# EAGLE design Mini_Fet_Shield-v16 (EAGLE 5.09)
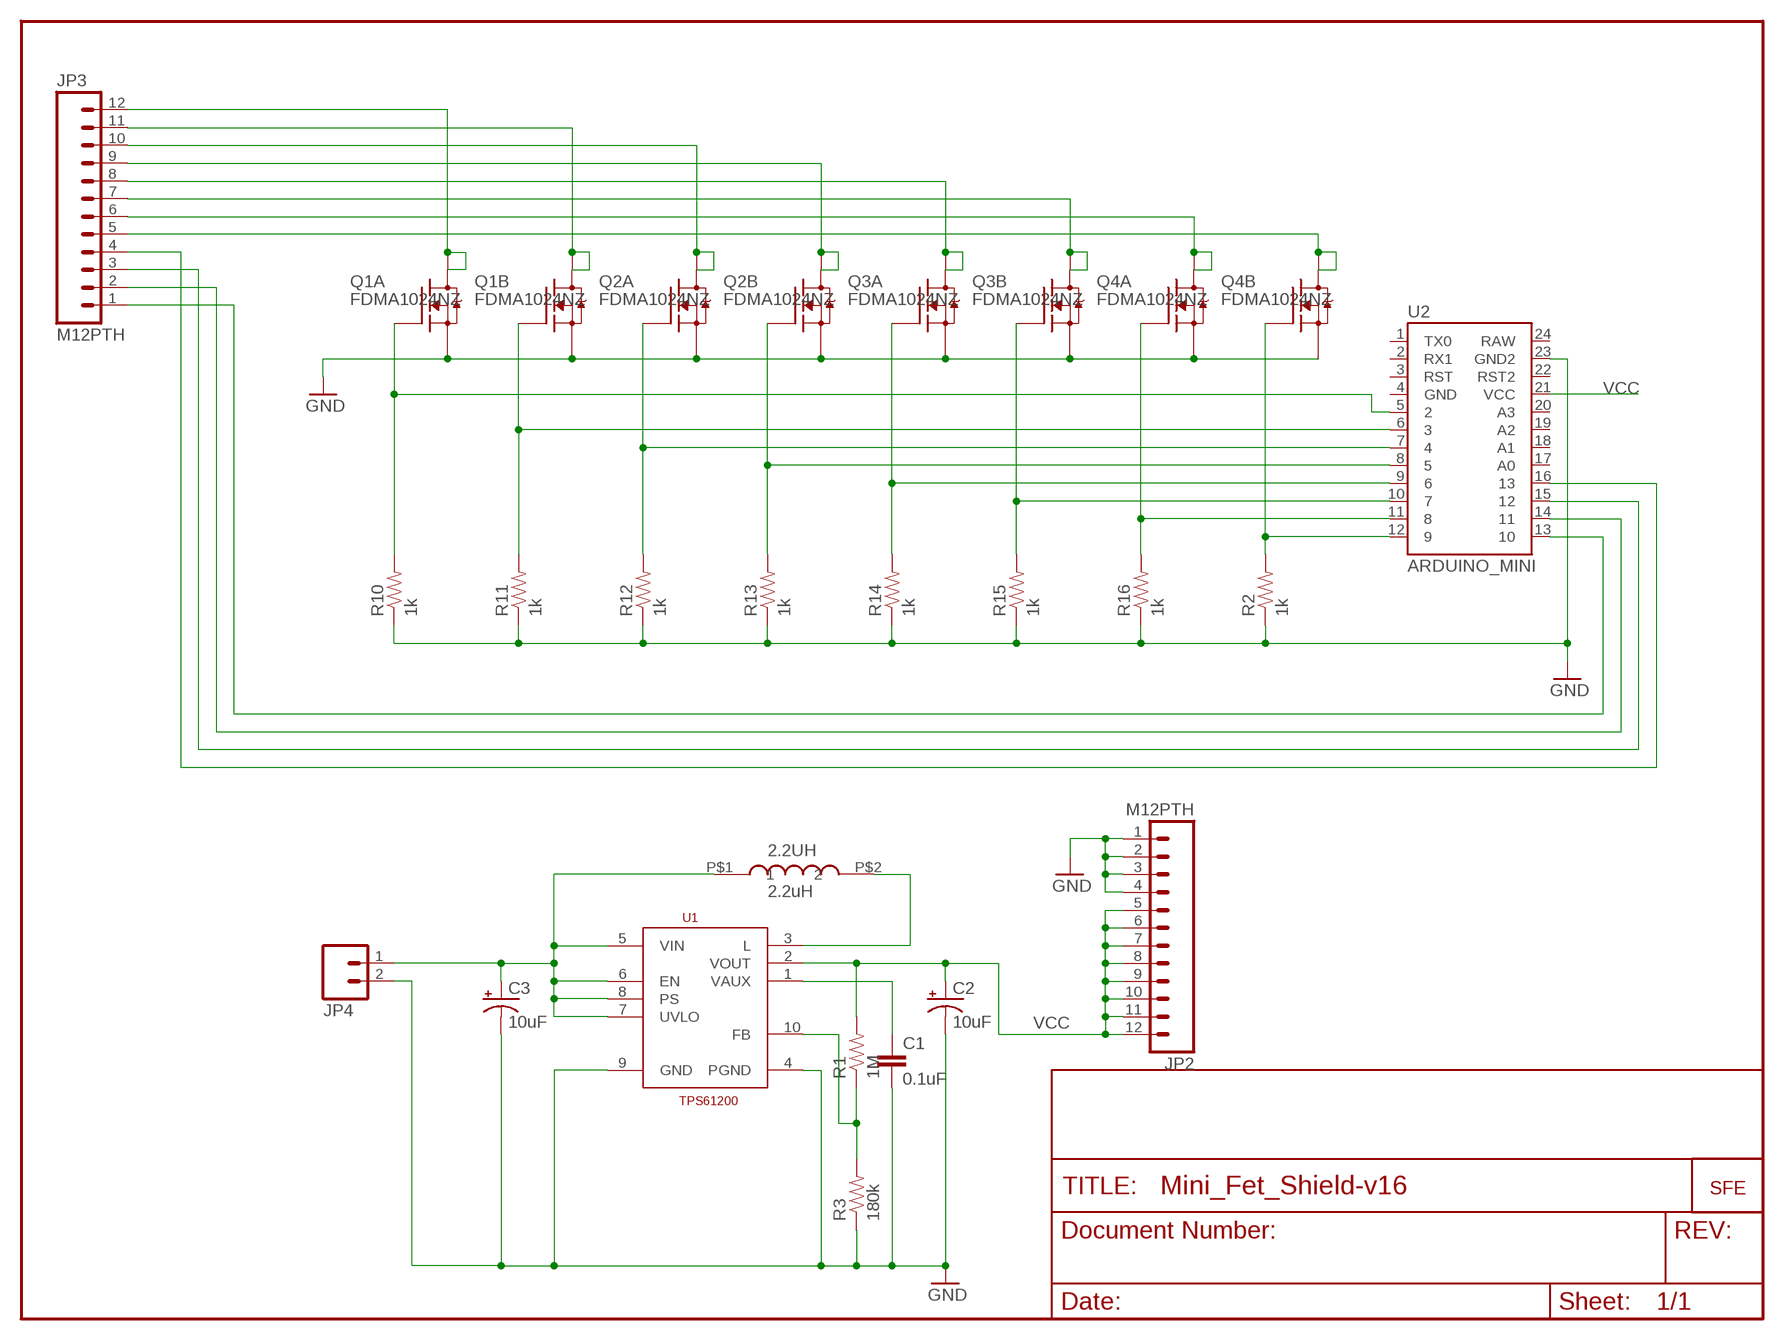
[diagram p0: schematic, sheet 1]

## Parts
2.2UH  2.2uH  VLF4012A  [VLF4012A]
C1  0.1uF  CAP0402-CAP  [0402-CAP]
C2  10uF  CAP_POL1206  [EIA3216]
C3  10uF  CAP_POL1206  [EIA3216]
JP2  M12PTH  [1X12]
JP3  M12PTH  [1X12]
JP4  M02PTH  [1X02]
JP5  LOGO-SFESK  [SFE-LOGO-FLAME]
Q1  FDMA1024NZ  [MICROFET_2X2]
Q2  FDMA1024NZ  [MICROFET_2X2]
Q3  FDMA1024NZ  [MICROFET_2X2]
Q4  FDMA1024NZ  [MICROFET_2X2]
R1  1M  RESISTOR0402-RES  [0402-RES]
R2  1k  RESISTOR0402-RES  [0402-RES]
R3  180k  RESISTOR0402-RES  [0402-RES]
R10  1k  RESISTOR0402-RES  [0402-RES]
R11  1k  RESISTOR0402-RES  [0402-RES]
R12  1k  RESISTOR0402-RES  [0402-RES]
R13  1k  RESISTOR0402-RES  [0402-RES]
R14  1k  RESISTOR0402-RES  [0402-RES]
R15  1k  RESISTOR0402-RES  [0402-RES]
R16  1k  RESISTOR0402-RES  [0402-RES]
U1  TPS61200  [DRC-S-PVSON-N10]
U2  ARDUINO_MINI  [ARDUINO_MINI]

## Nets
GND: C1.2 C2.C(-) C3.C(-) JP2.1 JP2.2 JP2.3 JP2.4 JP4.2 Q1.S1(A:S) Q1.S2(B:S) Q2.S1(A:S) Q2.S2(B:S) Q3.S1(A:S) Q3.S2(B:S) Q4.S1(A:S) Q4.S2(B:S) R2.1 R3.1 R10.1 R11.1 R12.1 R13.1 R14.1 R15.1 R16.1 U1.4(PGND) U1.9(GND) U2.23(GND2)
N$1: JP3.4 U2.16
N$2: R1.1 R3.2 U1.10(FB)
N$3: C1.1 U1.1(VAUX)
N$5: 2.2UH.P$2 U1.3(L)
N$7: Q1.G1(A:G) R10.2 U2.5
N$8: 2.2UH.P$1 C3.A(+) JP4.1 U1.5(VIN) U1.6(EN) U1.7(UVLO) U1.8(PS)
N$10: Q1.G2(B:G) R11.2 U2.6
N$11: Q2.G1(A:G) R12.2 U2.7
N$12: Q2.G2(B:G) R13.2 U2.8
N$13: Q3.G1(A:G) R14.2 U2.9
N$14: Q3.G2(B:G) R15.2 U2.10
N$15: Q4.G1(A:G) R16.2 U2.11
N$16: Q4.G2(B:G) R2.2 U2.12
N$17: JP3.12 Q1.D1(A:D) Q1.D1_2(A:D1)
N$18: JP3.11 Q1.D2(B:D) Q1.D2_2(B:D1)
N$19: JP3.10 Q2.D1(A:D) Q2.D1_2(A:D1)
N$20: JP3.9 Q2.D2(B:D) Q2.D2_2(B:D1)
N$21: JP3.8 Q3.D1(A:D) Q3.D1_2(A:D1)
N$22: JP3.7 Q3.D2(B:D) Q3.D2_2(B:D1)
N$23: JP3.6 Q4.D1(A:D) Q4.D1_2(A:D1)
N$24: JP3.5 Q4.D2(B:D) Q4.D2_2(B:D1)
N$25: JP3.3 U2.15
N$26: JP3.2 U2.14
N$27: JP3.1 U2.13
VCC: C2.A(+) JP2.5 JP2.6 JP2.7 JP2.8 JP2.9 JP2.10 JP2.11 JP2.12 R1.2 U1.2(VOUT) U2.21(VCC)
Unconnected: U2.1(TX0) U2.2(RX1) U2.3(RST) U2.4(GND) U2.17(A0) U2.18(A1) U2.19(A2) U2.20(A3) U2.22(RST2) U2.24(RAW)

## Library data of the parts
2.2UH = PEBBLE:VLF4012A
C1 = SparkFun:CAP: Capacitor
C2 C3 = SparkFun:CAP_POL: Capacitor Polarized
JP2 JP3 = SparkFun:M12: Header 12 Standard 12-pin 0.1" header. Use with straight break away headers (SKU : PRT-00116), right angle break away headers (PRT-00553), swiss pins (PRT-00743), machine pins (PRT-00117), and female headers (PRT-00115).
JP4 = SparkFun:M02: Header 2
JP5 = SparkFun:LOGO-SFE: Spark Fun Electronics PCB Logo
Q1-Q4 = PEBBLE:FDMA1024NZ: Dual N-Channel 30-V (D-S) MOSFET Source: http://www.vishay.com/docs/71053/71053.pdf
R1-R3 R10-R16 = SparkFun:RESISTOR: Resistor
U1 = texas:TPS61200
U2 = SparkFun:ARDUINO_MINI

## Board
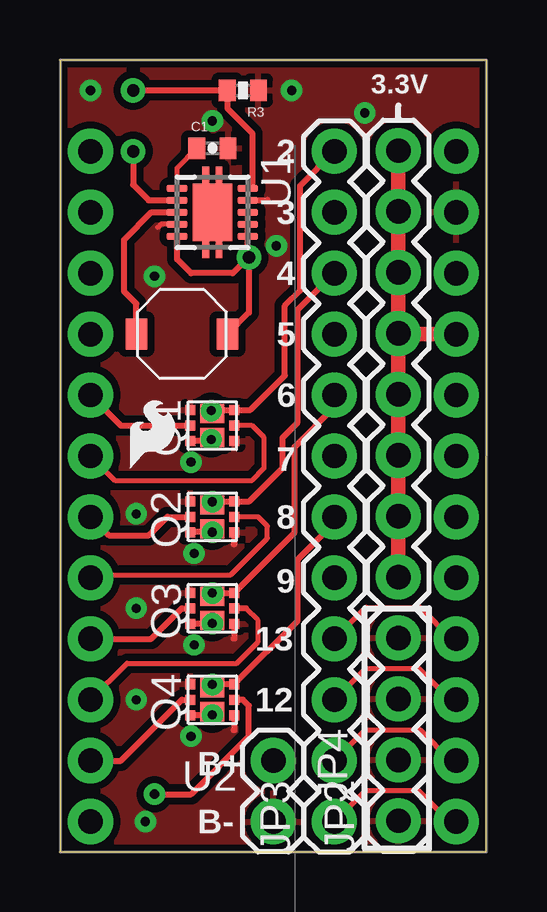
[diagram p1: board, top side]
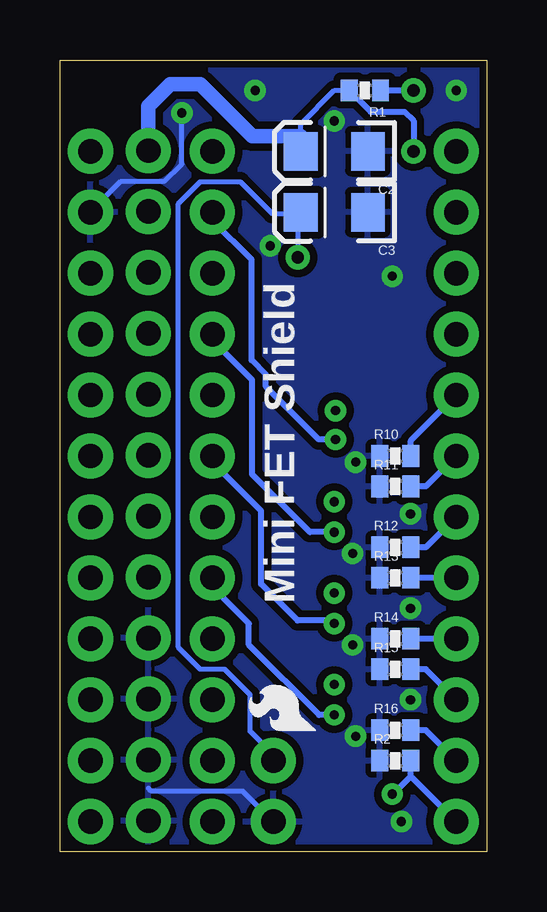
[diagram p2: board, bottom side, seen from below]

Size 17.78 x 33.02 mm. Coordinates in mm from the lower left corner, seen from the top.
Outline: 0,0 17.76,0 17.78,33.02 0,33.02 0,0
Copper layers (1*16): Top 0.035mm / dielectric 1.5mm / Bottom 0.035mm
Design rules "SparkFun": minimum track width 8mil, minimum drill 20mil, track to track 8mil, track to pad 8mil, pad to pad 8mil, via to via 8mil, smd to smd 8mil, copper to edge 8mil, drill to drill 8mil, minimum pad ring 12mil, minimum via ring 10mil, stop-mask expansion 4mil, vias tented up to drill 20mil, thermal gap 10mil

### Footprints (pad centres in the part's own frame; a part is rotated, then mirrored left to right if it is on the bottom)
VLF4012A = smd 0.9 x 1.3: P$1 -1.9,0; P$2 1.9,0
0402-CAP = smd 0.7 x 0.9: 1 -0.65,0; 2 0.65,0
EIA3216 = smd 1.4 x 1.6: A 1.4,0; C -1.4,0
1X12 = drill 1.016 pad 1.88 round: 1 0,0; 2 2.54,0; 3 5.08,0; 4 7.62,0; 5 10.16,0; 6 12.7,0; 7 15.24,0; 8 17.78,0; 9 20.32,0; 10 22.86,0; 11 25.4,0; 12 27.94,0
1X02 = drill 1.016 pad 1.88 round: 1 0,0; 2 2.54,0
MICROFET_2X2 = smd 0.8 x 1: D1 0.5,0; D2 -0.5,0 | smd 0.42 x 0.42: D1_2 0.65,-0.915; D2_2 -0.65,0.915; G1 0,0.915; G2 0,-0.915; S1 0.65,0.915; S2 -0.65,-0.915
0402-RES = smd 0.7 x 0.9: 1 -0.65,0; 2 0.65,0
DRC-S-PVSON-N10 = smd 0.28 x 0.85: 1 -1,-1.475; 2 -0.5,-1.475; 3 0,-1.475; 4 0.5,-1.475; 5 1,-1.475; 6 1,1.475; 7 0.5,1.475; 8 0,1.475; 9 -0.5,1.475; 10 -1,1.475 | smd 2.4 x 1.65: TH 0,0 | smd 3.8 x 0.28: TH@1 0,0.275; TH@2 0,-0.275
ARDUINO_MINI = drill 1.016 pad 1.88 round: 1 -7.62,12.7; 2 -7.62,10.16; 3 -7.62,7.62; 4 -7.62,5.08; 5 -7.62,2.54; 6 -7.62,0; 7 -7.62,-2.54; 8 -7.62,-5.08; 9 -7.62,-7.62; 10 -7.62,-10.16; 11 -7.62,-12.7; 12 -7.62,-15.24; 13 7.62,-15.24; 14 7.62,-12.7; 15 7.62,-10.16; 16 7.62,-7.62; 17 7.62,-5.08; 18 7.62,-2.54; 19 7.62,0; 20 7.62,2.54; 21 7.62,5.08; 22 7.62,7.62; 23 7.62,10.16; 24 7.62,12.7

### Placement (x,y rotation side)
2.2UH  5.08,21.59 180 top
C1  6.35,29.34 0 top
C2  6.35,29.21 180 bottom
C3  6.35,26.67 180 bottom
JP1  LOGO-SFESK  [SFE-LOGO-FLAME]  2.92,16 0 top
JP2  14.1,1.3 90 top
JP3  11.43,1.27 90 top
JP4  8.89,3.81 270 top
JP5  7.11,5.08 90 bottom
Q1  6.35,17.78 90 top
Q2  6.35,13.97 90 top
Q3  6.35,10.16 90 top
Q4  6.35,6.35 90 top
R1  5.08,31.75 180 bottom
R2  3.81,3.81 0 bottom
R3  7.62,31.75 180 top
R10  3.81,16.51 0 bottom
R11  3.81,15.24 0 bottom
R12  3.81,12.7 0 bottom
R13  3.81,11.43 0 bottom
R14  3.81,8.89 0 bottom
R15  3.81,7.62 0 bottom
R16  3.81,5.08 0 bottom
U1  6.35,26.67 270 top
U2  8.89,16.51 0 top

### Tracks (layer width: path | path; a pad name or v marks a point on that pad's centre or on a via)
GND  (via drill 0.38)
  Top 0.203: U1.4 4.2,26.17 4.06,26.04
  Top 0.254: Q4.S2 7.26,5.08 7.24,5.08 | Q3.S2 7.26,8.89 7.24,8.89 | Q2.S2 7.26,12.83 7.24,12.83 | U1.9 8.64,27.18
  Bottom 0.203: JP4.2 10.16,2.54 13.97,2.54 14.1,2.67 | U2.23 15.24,27.96 13.44,27.96 12.7,28.68 12.7,30.68 12.72,30.71
  other vias: 3.56,1.27 3.17,14.1 3.17,10.16 3.17,6.35 5.46,16.26 5.59,12.45 5.59,8.64 1.27,31.75 5.46,4.83 3.94,24 9.65,31.75 6.35,30.48 9.02,25.27 12.7,30.81
  pour Top (isolate 0.305): 0,33.02 0,0 17.78,0 17.78,33.02
  pour Bottom (isolate 0.305): 0,33.02 0,0 17.78,0 17.78,33.02
N$1
  Top 0.203: U2.16 16.31,8.89 15,10.2 12.74,10.2 JP3.4
N$2  (via drill 0.51)
  Top 0.254: v3.05,31.75 R3.2 6.97,31 8,29.97 8,27.85 U1.10
  Bottom 0.254: R1.1 v3.05,31.75
N$3
  Top 0.203: U1.1 4.88,28.51 C1.1
N$5
  Top 0.254: U1.3 3.81,26.67 2.67,25.53 2.67,23.37 3.18,22.86 2.2UH.P$2
N$7
  Top 0.254: Q1.G1 2.54,17.78 U2.5
  Bottom 0.254: R10.2 3.16,17.16 U2.5
N$8  (via drill 0.51)
  Top 0.203: U1.8 7.82,26.26 U1.7 | v7.87,24.79 7.83,24.77
  Top 0.254: U1.5 4.88,24.72 5.46,24.13 7.19,24.13 7.83,24.77 U1.6 U1.7 | 2.2UH.P$1 7.87,22.48 v7.87,24.79
  Bottom 0.203: v7.87,24.79 7.87,26.57 7.77,26.67 C3.A 7.92,26.62 8.94,26.62 10.26,27.94 11.94,27.94 12.85,27.03 12.85,8.53 11.94,7.62 10.92,7.62 9.86,6.55 9.86,5.03 8.89,4.06 JP4.1
N$10
  Top 0.203: Q1.G2 8,17.78 8.51,17.27 8.51,16 8,15.49 2.29,15.49 U2.6
  Bottom 0.254: R11.2 2.54,15.24 U2.6
N$11
  Top 0.254: Q2.G1 4.47,13.97 3.7,13.2 2.04,13.2 U2.7
  Bottom 0.254: R12.2 2.54,12.7 U2.7
N$12
  Top 0.203: Q2.G2 8.26,13.97 8.64,13.59 8.64,13.08 7.11,11.56 1.4,11.56 U2.8
  Bottom 0.254: U2.8 R13.2
N$13
  Top 0.254: Q3.G1 5.08,10.16 3.81,8.89 U2.9
  Bottom 0.254: U2.9 R14.2
N$14
  Top 0.203: 7.75,10.16 8.26,9.65 8.26,8.76 7.37,7.87 2.79,7.87 U2.10
  Top 0.254: 7.75,10.16 Q3.G2
  Bottom 0.254: R15.2 2.54,7.62 U2.10
N$15
  Top 0.254: Q4.G1 5.08,6.35 2.54,3.81 U2.11
  Bottom 0.254: R16.2 2.54,5.08 U2.11
N$16  (via drill 0.38)
  Top 0.254: Q4.G2 7.62,6.35 7.87,6.1 7.87,4.83 5.46,2.41 v3.94,2.41
  Bottom 0.254: 3.16,3.16 R2.2 | U2.12 3.16,3.16 | 3.16,3.16 3.91,2.41 v3.94,2.41
N$17  (via drill 0.38)
  Top 0.254: v6.3,18.4 6.35,18.35 Q1.D1 6.5,18.43 Q1.D1_2 7.93,18.43 9.37,19.87 9.37,22.77 10,23.4 10,27.78 JP3.12
N$18  (via drill 0.38)
  Top 0.254: Q1.D2_2 6.23,17.13 v6.3,17.2 6.3,17.23 Q1.D2
  Bottom 0.254: JP3.11 11.43,26.33 9.8,24.7 9.8,20.5 9.2,19.9 9.2,19.4 7,17.2 6.43,17.2 Q1.D2 6.35,17.25 v6.3,17.2
N$19  (via drill 0.38)
  Top 0.254: JP3.10 9.91,22.61 9.91,17.91 9.27,17.27 9.27,16 7.89,14.62 Q2.D1_2 7.25,14.61 v6.35,14.61 Q2.D1
N$20  (via drill 0.38)
  Top 0.254: Q2.D2_2 5.45,13.34 v6.35,13.34 Q2.D2
  Bottom 0.254: JP3.9 11.43,21.34 9.78,19.68 9.78,15.75 7.37,13.34 v6.35,13.34
N$21  (via drill 0.38)
  Top 0.254: v6.35,10.79 Q3.D1 6.5,10.81 Q3.D1_2 9.78,13.32 9.78,16.89 11.43,18.54 JP3.8
N$22  (via drill 0.38)
  Top 0.254: Q3.D2_2 6.33,9.51 v6.35,9.53 Q3.D2
  Bottom 0.254: JP3.7 11.43,16.26 9.4,14.22 9.4,11.18 7.87,9.65 6.48,9.65 v6.35,9.53
N$23  (via drill 0.38)
  Top 0.254: JP3.6 10.92,13.46 10.92,13.21 9.91,12.19 9.91,9.64 Q4.D1_2 6.37,7 v6.35,6.99 Q4.D1
N$24  (via drill 0.38)
  Top 0.254: Q4.D2_2 6.33,5.7 v6.35,5.71 Q4.D2
  Bottom 0.254: v6.35,5.71 6.99,5.71 9.91,8.64 9.91,9.53 11.43,11.05 JP3.5
N$25
  Top 0.203: U2.15 16.25,6.35 14.95,7.65 12.73,7.65 JP3.3
N$26
  Top 0.203: U2.14 16.29,3.81 15,5.1 12.72,5.1 JP3.2
N$27
  Top 0.203: U2.13 16.23,1.27 14.92,2.58 12.74,2.58 JP3.1
VCC  (via drill 0.51)
  Top 0.254: U1.2 3.69,27.17 3.05,27.81 v3.05,29.21
  Top 0.61: JP2.5 JP2.6 JP2.7 JP2.8 JP2.9 | JP2.9 JP2.10 JP2.11 JP2.12 | U2.21 14.13,21.59 JP2.9
  Bottom 0.203: 7.75,29.84 7.75,30.35 6.35,31.75 R1.2
  Bottom 0.254: 5.84,31.75 R1.2 4.84,30.86 3.43,30.86 3.05,30.48 v3.05,29.21 | 7.75,29.84 C2.A
  Bottom 0.61: 7.75,29.84 9.78,29.84 11.94,32 13.18,32 14.1,31.09 JP2.12

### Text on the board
tPlace: 3.3V | 2 | 3 | 4 | 5 | 6 | 7 | 8 | 9 | 13 | 12 | B+ | B-
bPlace: Mini FET Shield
